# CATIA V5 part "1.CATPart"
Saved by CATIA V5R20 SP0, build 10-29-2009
Part number: 1
Bounding box of the stored display mesh (mm): x -43 to 42.999, y -43 to 43, z -62.993 to 262.999
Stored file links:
  E:\Ehsan\Amoozesh\CATIA\CATIA Course\Advanced\Videos\Session-25\1.CATPart
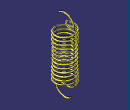
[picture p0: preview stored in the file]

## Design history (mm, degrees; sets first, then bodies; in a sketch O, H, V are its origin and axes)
AxisSystem1: origin (0, 0, 0), X (1, 0, 0), Y (0, 1, 0), Z (0, 0, 1)
Set1
  Point1: (0, 40, 0), in AxisSystem1
  Helix1: Direction edge [ZX plane of AxisSystem1 | YZ plane of AxisSystem1], RefPoint Point1, Pitch 15, Height 200, TaperAngle 0
  Sketch1 on YZ plane of AxisSystem1, origin (0, 0, 0), H (0, 1, 0), V (0, 0, 1)
    arc A1 centre (0, 220) radius 40 from (40, 220) to (-25.7115, 250.6418) ccw
    point P1 (0, 220)
    point P2 (40, 220)
    construction line L1 (0, 220) -> (40, 220)
    construction line L2 (0, 220) -> (-25.7115, 250.6418)
    reference projected point E1 (-20, 200) from vertex of Helix1
    construction line L3 (-78.7247, 100) -> (76.9398, 100)
    point P4 (-78.7247, 100)
    arc A2 centre (0, -20) radius 40 from (-40, -20) to (25.7115, -50.6418) ccw
    angle L1 L2 = 130
    distance L1 E1 = 20
    distance P4 H = 100
    radius A1 = 40
    radius A2 = 40
    coincidence: P1 V
    horizontal: L1 H, L3 H
  Connect1: Curve1 Sketch1, Point1 Sketch1.P2, Tension1 1, Curve2 Helix1, Point2 vertex of Helix1, Tension2 1
  Connect2: Curve1 Helix1, Point1 Point1, Tension1 1, Curve2 sketch element, Point2 vertex of Sketch1, Tension2 1
  Join1: Elements (sketch element; Connect2; Helix1; Connect1; Sketch1)
  Sweep1: type Circle, Guide Join1, Radius 3
Body1 (main body)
